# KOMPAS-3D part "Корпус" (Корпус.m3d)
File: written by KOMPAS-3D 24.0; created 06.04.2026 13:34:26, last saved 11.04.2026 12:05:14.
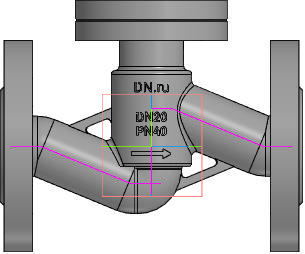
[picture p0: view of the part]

Document properties: Автор: R2D2; Полное имя файла: E:\Работа\Зайцев\VSO3131M-F-S Клапан запорный DN.ru Ду15-100 Ру40\DN20\исходные материалы\Корпус.m3d

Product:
- Body: Труба / Нестандартная труба / L = 73.6 мм  | qty 1
    Материал: Нестандартная труба (density 7856 kg/m3)
    Масса: 3.508918
    Раздел спецификации: Детали
    Примечание: 0,41 кг
    additional columns: Pipeline; 0.03; 0; 0; 0.002; 0.07364; true; 0.04
- Body: Труба / Нестандартная труба / L = 89.3 мм  | qty 1
    Материал: Нестандартная труба (density 7856 kg/m3)
    Масса: 3.508918
    Раздел спецификации: Детали
    Примечание: 0,5 кг
    additional columns: Pipeline; 0.03; 0; 0; 0.002; 0.08927; true; 0.04
- Body: Тело 4  | qty 1
    Материал: Нестандартная труба (density 7856 kg/m3)
    Масса: 3.508918
- Body: Тело 5  | qty 1
    Материал: Нестандартная труба (density 7856 kg/m3)
    Масса: 3.508918
- Part/product: Корпус
    Масса: 6.9

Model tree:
1. Труба
2. Труба:1  (labels: {F703FF30-5BE6-4673-A7F1-8EDA1BE1E2D1}; SHAPEOBJECT3D_ATTR_BUTT; SHAPEOBJECT3D_ATTR_VALID; SHAPEOBJECT3D_ATTR_BUTT_AREA)
     PIPE_R = 7
3. Труба:2  (labels: {F703FF30-5BE6-4673-A7F1-8EDA1BE1E2D1}; SHAPEOBJECT3D_ATTR_BUTT; SHAPEOBJECT3D_ATTR_VALID; SHAPEOBJECT3D_ATTR_BUTT_AREA)
     PIPE_R = 7
4. Колонна
5. Элемент выдавливания:1
     Смещение 1 = -1; Смещение 2 = -5
6. Скругление:17  (with: Ребро.Элемент выдавливания:1)
     Радиус = 1
7. Скругление:18  (with: Ребро.Элемент выдавливания:1)
8. Скругление:24  (with: Ребро.Элемент выдавливания:1)
     Радиус = 1.5
9. Элемент выдавливания:2
     Расстояние 1 = 6
10. Скругление:19  (with: Ребро.Элемент выдавливания:2)
     Радиус = 2
11. Эскиз:4  (with: Грань.Элемент выдавливания:1)
12. Элемент выдавливания:3
     Расстояние 1 = 15
13. Скругление:21  (with: Ребро.Элемент выдавливания:3)
14. ОТЛИВКА
15. Скругление:6  (with: Грань.Элемент выдавливания:1)
     Радиус = 2
16. Элемент выдавливания:6  (with: Грань.Элемент выдавливания:1)
     Смещение 1 = 4
17. ЛЕЙБЛ
18. Элемент выдавливания:7  (with: Грань.Элемент выдавливания:1)
     Расстояние 1 = 20.9933; Смещение 1 = 1
19. Фланец верх  (with: Ребро.Элемент выдавливания:3)
20. Элемент вращения:2
     Угол 1 = 360
21. Эскиз:12  (with: Грань.Элемент вращения:2)
22. Элемент выдавливания:9  (with: Грань.Элемент вращения:2)
     Расстояние 2 = 20
23. Массив по концентрической сетке:1  (with: Элемент выдавливания:9, Эскиз:12, Грань.Элемент вращения:2)  (4 pattern instances)
     Шаг 2 = 360
24. Фланец
25. Элемент вращения:1
     Угол 1 = 360
26. Эскиз:10  (with: Грань.Элемент вращения:1)
27. Элемент выдавливания:8
28. Массив по концентрической сетке:2  (with: Элемент выдавливания:8, Эскиз:10, Грань.Элемент вращения:1)  (4 pattern instances)
     Шаг 2 = 360
29. Зеркальный массив:1
30. Экземпляр ( 1 )
31. Экземпляр ( 2 )  (with: Элемент вращения:1, Массив по концентрической сетке:2, Экземпляр ( 1 ), Элемент выдавливания:8)
32. Экземпляр ( 3 )  (with: Элемент выдавливания:8)
33. Экземпляр ( 4 )  (with: Элемент выдавливания:8)

Expressions: DS/2+3; D1/2; DN/2; D/2; DS-v977*4; LL/2; D1-v1234*2
Referenced files in C:\Program Files\ASCON\KOMPAS-3D v24\Libs\Pipeline\: StylesTemplate.a3d, TemplateHPH, InsulationStylesTemplate.a3d, Insulation
Referenced files in C:\Program Files\ASCON\KOMPAS-3D v24\Templates\: Констр. чертеж А3 гориз. перв. лист.cdt
Referenced files in E:\Работа\Зайцев\VSO3131M-F-S Клапан запорный DN.ru Ду15-100 Ру40\DN20\исходные материалы\: 
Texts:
  Отводы ГОСТ 17375-2001
  Констр. чертеж А3 гориз. перв. лист.cdt
  GOST 26.020 Pr3
  var3D
  GOST 2.304 type A
  PN40
  смещение колонны вниз
  LL-10
  DN+10
  Труба / Нестандартная труба / L = %s мм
